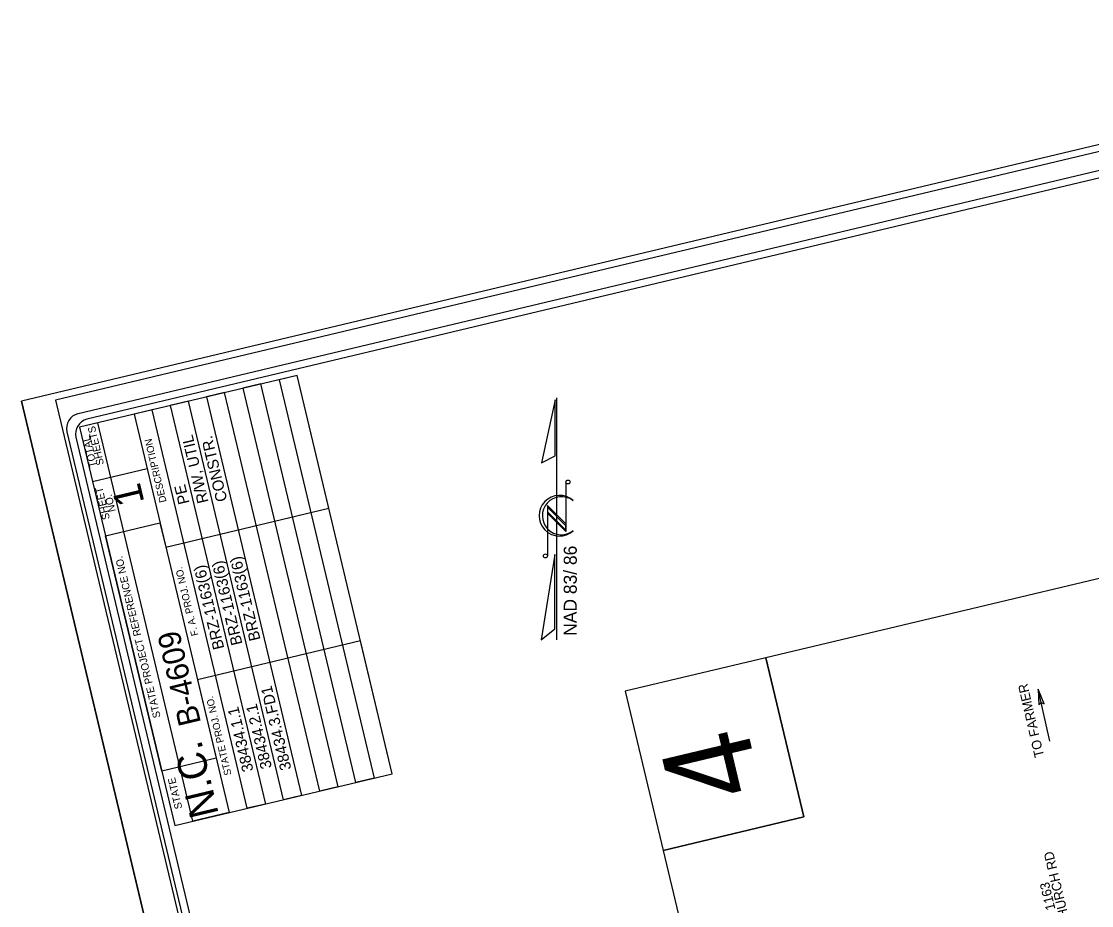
# Model space of a CAD drawing. Extents: x 1734738 to 1742883, y 698103 to 703125.
# Drawn here: x 1734738 to 1736174, y 700702 to 701889 of the extents above; entities that cross this region are included whole.
import ezdxf

# ---------------------------------------------------------------- set-up
doc = ezdxf.new("R2010")
doc.units = 0
for name, color, linetype in [('Exist Cultural Recreational Athletic Track', 7, 'Continuous'), ('Exist Map Preparation Border Sheet 1 CELL', 7, 'Continuous'), ('Exist Road Primary US Shield CELL', 7, 'Continuous'), ('Exist Road Primary US Structure Standard Bridge Number Label', 7, 'Continuous'), ('Exist Road Secondary Structure Pipe Number Label', 7, 'Continuous'), ('Exist Road Secondary Type 41 Number Label', 7, 'Continuous'), ('Exist Road Secondary Type 41 SR Number Label', 7, 'Continuous'), ('Exist Road Secondary Type 51 Divided Label', 7, 'Continuous'), ('Level 56', 7, 'Continuous')]:
    doc.layers.add(name, color=color, linetype=linetype)

msp = doc.modelspace()

# ---------------------------------------------------------------- linework, layer by layer
at = {"layer": 'Exist Cultural Recreational Athletic Track'}
msp.add_line((1736118.2, 700922.6), (1736102.4, 700992.1), dxfattribs=at)
at = {"layer": 'Exist Road Primary US Shield CELL'}
for points in [[(1735867.2, 699650.6), (1736804.2, 699873.9), (1736485.1, 701212.6), (1735736.8, 701034.2), (1735787.7, 700820.7), (1735599, 700775.7)], [(1735787.7, 700820.7), (1735736.8, 701034.2), (1735548.1, 700989.3), (1735599, 700775.7)]]:
    msp.add_lwpolyline(points, close=True, dxfattribs=at)
at = {"layer": 'Exist Road Primary US Structure Standard Bridge Number Label'}
msp.add_line((1735518.8, 698102.6), (1734738, 701378.8), dxfattribs=at)
at = {"layer": 'Exist Road Secondary Structure Pipe Number Label'}
msp.add_lwpolyline([(1737609.2, 698627.6), (1736836.4, 701869.7), (1734783.7, 701380.5), (1735556.5, 698138.3)], close=True, dxfattribs=at)
at = {"layer": 'Exist Road Secondary Type 41 Number Label'}
msp.add_lwpolyline([(1736110.3, 700972.7), (1736102.4, 700992.1), (1736103.3, 700971), (1736106.3, 700974.4)], close=True, dxfattribs=at)
at = {"layer": 'Exist Road Secondary Type 41 SR Number Label'}
msp.add_lwpolyline([(1734738, 701378.8), (1735518.8, 698102.6), (1737658.8, 698612.7), (1736878, 701888.9)], close=True, dxfattribs=at)
at = {"layer": 'Exist Road Secondary Type 51 Divided Label'}
for points in [[(1736817.8, 701839.6), (1734813.9, 701362)], [(1736450.5, 701741.8), (1734825.9, 701354.6)], [(1735235.5, 700878.6), (1735108, 701413.6), (1735083.7, 701407.8), (1735211.2, 700872.8), (1735186.9, 700867), (1735059.3, 701402), (1735035, 701396.2), (1735162.5, 700861.2), (1735138.2, 700855.4), (1735010.7, 701390.4), (1734986.4, 701384.6), (1735113.9, 700849.6), (1735089.6, 700843.8), (1734962, 701378.8), (1734937.7, 701373), (1735065.3, 700838), (1735040.9, 700832.2), (1734913.4, 701367.2), (1734889.1, 701361.4), (1735016.6, 700826.4), (1734968, 700814.8), (1734840.4, 701349.8), (1734816.1, 701344), (1734943.7, 700809), (1735235.5, 700878.6), (1735193, 701056.9), (1734974.1, 701004.7), (1734999.2, 700899.4), (1734926.3, 700882), (1734850.9, 701198.1), (1734923.9, 701215.5), (1734931.6, 701183), (1735150.5, 701235.2), (1735108, 701413.6), (1734816.1, 701344), (1734833.5, 701271.1), (1734906.5, 701288.5)], [(1734799.1, 701337.9), (1735485.4, 698458.5)], [(1734811.2, 701330.5), (1735469.6, 698567.9)]]:
    msp.add_lwpolyline(points, dxfattribs=at)
for centre in [(1734818.5, 701342.5), (1734830.5, 701335.1)]:
    msp.add_arc(centre, 20, 103.4059, 193.4059, dxfattribs=at)
at = {"layer": 'Level 56'}
for p, q in [((1735456.5, 701058.6), (1735456.5, 701383.6)), ((1735468.7, 701270.5), (1735468.7, 701203.8)), ((1735477.9, 701245.6), (1735478.3, 701245.4)), ((1735468.7, 701214.2), (1735443.9, 701239)), ((1735443.9, 701239), (1735443.9, 701171.2)), ((1735468.7, 701211.7), (1735443.9, 701236.6)), ((1735443.9, 701236.6), (1735443.9, 701230.5)), ((1735468.7, 701205.6), (1735443.9, 701230.5)), ((1735443.9, 701230.5), (1735468.7, 701205.6)), ((1735468.7, 701203.8), (1735443.9, 701228.6)), ((1735468.7, 701205.6), (1735468.7, 701211.7))]:
    msp.add_line(p, q, dxfattribs=at)
for points in [[(1735454.2, 701380.7), (1735435.7, 701296.3), (1735454.2, 701305.7)], [(1735453.8, 701173.1), (1735435.4, 701058.6), (1735453.8, 701073.1)]]:
    msp.add_lwpolyline(points, close=True, dxfattribs=at)
for centre in [(1735471.4, 701270.4), (1735441.2, 701171.1)]:
    msp.add_circle(centre, 2.65, dxfattribs=at)
for centre, radius, start, end in [((1735460, 701225.1), 27.3, 47.8401, 312.3941), ((1735462.6, 701225.1), 25.6, 53.0951, 308.6288)]:
    msp.add_arc(centre, radius, start, end, dxfattribs=at)

# ---------------------------------------------------------------- texts
at = {"layer": 'Exist Cultural Recreational Athletic Track'}
for s, height, rotation, p in [('TO FARMER', 12.84, 103.0308, (1736110.5, 700902.2)), ('UNION CHURCH RD', 12.844, 103.4845, (1736160.4, 700615.9)), ('SR 1163', 12.84, 103.4845, (1736132.3, 700669.1))]:
    msp.add_text(s, height=height, rotation=rotation, dxfattribs=at).set_placement(p)
at = {"layer": 'Exist Map Preparation Border Sheet 1 CELL'}
for s, height, p in [('R/W, UTIL ', 15, (1734989.2, 701243.7)), ('CONSTR.   ', 15, (1735014.4, 701245.8)), ('   PE     ', 15, (1734967.5, 701226.1)), ('BRZ-1163(6)   ', 15, (1735058.9, 701058.9)), ('BRZ-1163(6)   ', 15, (1735010.3, 701047.3)), ('BRZ-1163(6)   ', 15, (1735034.7, 701053.1)), ('B-4609    ', 30, (1734979.2, 700947)), ('38434.3.FD1', 15, (1735100.4, 700885.1)), ('38434.1.1 ', 15, (1735049.5, 700883)), ('38434.2.1 ', 15, (1735074.2, 700887))]:
    msp.add_text(s, height=height, rotation=103.4059, dxfattribs=at).set_placement(p)
at = {"layer": 'Exist Road Primary US Shield CELL'}
msp.add_text('4', height=120.4, rotation=103.4059, dxfattribs=at).set_placement((1735731.2, 700858.4))
at = {"layer": 'Exist Road Secondary Type 51 Divided Label'}
for s, height, p in [('SHEETS', 10, (1734848.9, 701294.2)), ('TOTAL', 10, (1734839.3, 701291.3)), ('DESCRIPTION', 9.6, (1734932.8, 701244)), ('SHEET', 10, (1734856.8, 701221)), ('1', 38.7, (1734903.2, 701243.2)), ('NO.', 10, (1734864.5, 701231.4)), ('STATE PROJECT REFERENCE NO.', 10, (1734924.9, 700954.8)), ('F. A. PROJ. NO.', 9.6, (1734975.5, 701064.9)), ('STATE PROJ. NO.', 9.6, (1735020.1, 700877.5)), ('N.C.', 38.7, (1735002.9, 700824.7)), ('STATE', 10, (1734954, 700832.5))]:
    msp.add_text(s, height=height, rotation=103.4059, dxfattribs=at).set_placement(p)
at = {"layer": 'Level 56'}
msp.add_text('NAD 83/ 86', height=17.5, rotation=90, dxfattribs=at).set_placement((1735483.2, 701063.9))

doc.saveas('drawing.dxf')
